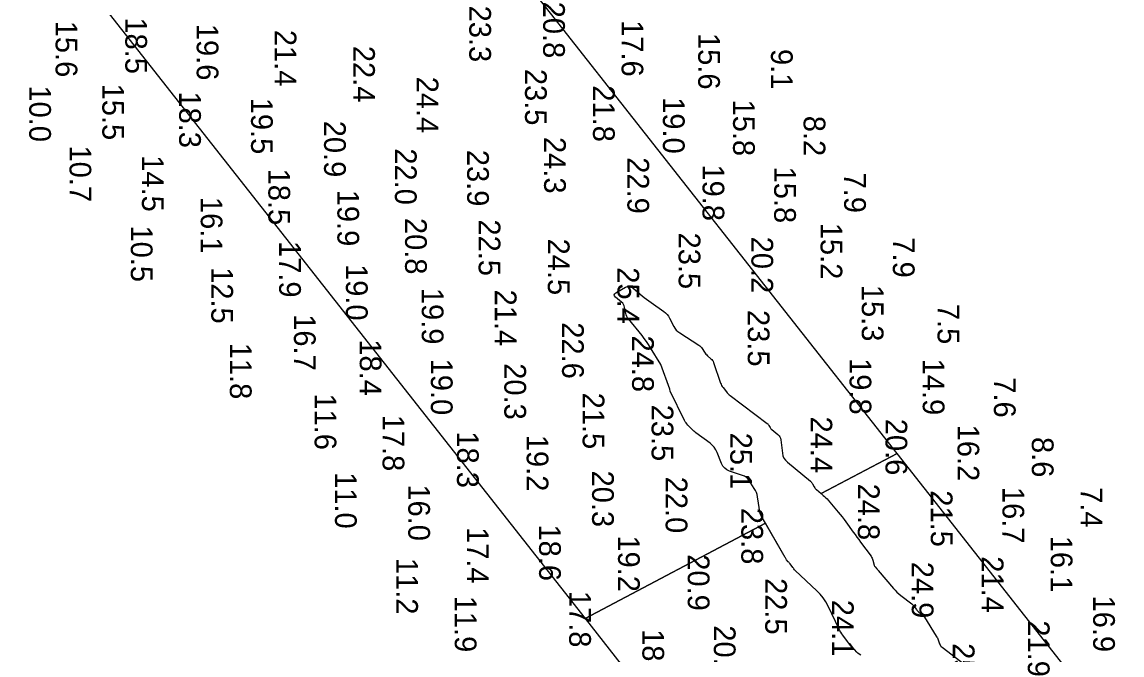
# Model space of a CAD drawing. Extents: x 1178573 to 1187098, y 693282 to 751751.
# Drawn here: x 1183878 to 1184511, y 737960 to 738324 of the extents above; entities that cross this region are included whole.
import ezdxf

# ---------------------------------------------------------------- set-up
doc = ezdxf.new("R2010")
doc.units = 0
for name, color, linetype in [('G-ANNO-PATT', 7, 'Continuous'), ('V-HYDS-MAJR', 7, 'Continuous'), ('V-HYDS-SOUN', 7, 'Continuous')]:
    doc.layers.add(name, color=color, linetype=linetype)

msp = doc.modelspace()

# ---------------------------------------------------------------- linework, layer by layer
at = {"layer": 'G-ANNO-PATT'}
for p, q in [((1184381.59, 738075.66), (1183884.78, 738706.45)), ((1184337.84, 738052.53), (1184381.59, 738075.66)), ((1184381.59, 738075.66), (1184337.84, 738052.53)), ((1184698.75, 737672.97), (1184381.59, 738075.66)), ((1184201.87, 737980.6), (1184305.67, 738035.51)), ((1184305.67, 738035.51), (1184201.87, 737980.6)), ((1184317.07, 738015.86), (1184305.67, 738035.51)), ((1184317.21, 738015.49), (1184317.07, 738015.86)), ((1184317.38, 738015.13), (1184317.21, 738015.49)), ((1184317.59, 738014.8), (1184317.38, 738015.13)), ((1184317.84, 738014.49), (1184317.59, 738014.8)), ((1184318.9, 738013.29), (1184317.84, 738014.49)), ((1184319.17, 738012.99), (1184318.9, 738013.29)), ((1184319.43, 738012.68), (1184319.17, 738012.99)), ((1184319.68, 738012.37), (1184319.43, 738012.68)), ((1184319.92, 738012.05), (1184319.68, 738012.37)), ((1184321.45, 738010.02), (1184319.92, 738012.05)), ((1184321.8, 738009.58), (1184321.45, 738010.02)), ((1184322.16, 738009.16), (1184321.8, 738009.58)), ((1184322.54, 738008.76), (1184322.16, 738009.16)), ((1184322.94, 738008.37), (1184322.54, 738008.76)), ((1184335.35, 737996.66), (1184322.94, 738008.37)), ((1184337.28, 737994.66), (1184335.35, 737996.66)), ((1184339, 737992.52), (1184337.28, 737994.66)), ((1184340.52, 737990.23), (1184339, 737992.52)), ((1184341.83, 737987.79), (1184340.52, 737990.23)), ((1184348.17, 737974.62), (1184341.83, 737987.79)), ((1184201.87, 737980.6), (1184742.06, 737294.73)), ((1184348.65, 737973.67), (1184348.17, 737974.62)), ((1184349.18, 737972.75), (1184348.65, 737973.67)), ((1184349.76, 737971.86), (1184349.18, 737972.75)), ((1184350.38, 737970.99), (1184349.76, 737971.86)), ((1184353.01, 737967.48), (1184350.38, 737970.99)), ((1184353.63, 737966.68), (1184353.01, 737967.48)), ((1184354.26, 737965.89), (1184353.63, 737966.68)), ((1184354.91, 737965.12), (1184354.26, 737965.89)), ((1184355.57, 737964.37), (1184354.91, 737965.12)), ((1184358.27, 737961.37), (1184355.57, 737964.37)), ((1184358.98, 737960.67), (1184358.27, 737961.37)), ((1184359.76, 737960.07), (1184358.98, 737960.67)), ((1184360.6, 737959.58), (1184359.76, 737960.07))]:
    msp.add_line(p, q, dxfattribs=at)
for points in [[(1183555.03, 739077.67), (1183691.64, 738653.74), (1183705.44, 738610.92), (1184201.87, 737980.6)], [(1184305.67, 738035.51), (1184303.49, 738039.27), (1184303.02, 738040.03), (1184302.75, 738040.96), (1184301.2, 738050.68), (1184300.92, 738051.97), (1184300.52, 738053.2), (1184299.99, 738054.39), (1184299.33, 738055.52), (1184296.44, 738059.97), (1184295.66, 738060.99), (1184294.73, 738061.84), (1184293.68, 738062.52), (1184292.48, 738063.03), (1184285.05, 738065.5), (1184283.53, 738066.18), (1184282.26, 738067.13), (1184281.24, 738068.34), (1184280.48, 738069.82), (1184277.91, 738076.25), (1184277.17, 738077.79), (1184276.25, 738079.18), (1184275.14, 738080.43), (1184273.83, 738081.52), (1184265.72, 738087.49), (1184265.08, 738087.99), (1184264.46, 738088.51), (1184263.86, 738089.05), (1184263.29, 738089.63), (1184261.04, 738091.98), (1184260.5, 738092.59), (1184260.02, 738093.23), (1184259.58, 738093.9), (1184259.2, 738094.62), (1184250.93, 738111.42), (1184250.76, 738112.69), (1184245.45, 738126.79), (1184239.6, 738136.48), (1184238.46, 738138.3), (1184237.25, 738140.08), (1184235.99, 738141.81), (1184234.66, 738143.5), (1184226.91, 738152.99), (1184226.38, 738153.72), (1184225.96, 738154.49), (1184225.63, 738155.31), (1184225.39, 738156.18), (1184224.66, 738159.74), (1184224.41, 738160.59), (1184224.04, 738161.37), (1184223.54, 738162.07), (1184222.91, 738162.7), (1184219.46, 738165.62), (1184218.87, 738166.29), (1184218.7, 738166.92), (1184218.97, 738167.51), (1184219.67, 738168.06), (1184225.09, 738171.23), (1184226.28, 738171.74), (1184227.43, 738171.83), (1184228.54, 738171.53), (1184229.62, 738170.81), (1184234.78, 738166.34), (1184236, 738165.31), (1184237.26, 738164.31), (1184238.54, 738163.35), (1184239.84, 738162.42), (1184247.16, 738157.36), (1184248.19, 738156.55), (1184249.1, 738155.64), (1184249.88, 738154.61), (1184250.55, 738153.48), (1184252.96, 738148.74), (1184253.62, 738147.62), (1184254.42, 738146.61), (1184255.34, 738145.72), (1184256.4, 738144.94), (1184267.44, 738137.85), (1184267.97, 738137.47), (1184268.45, 738137.04), (1184268.88, 738136.56), (1184269.26, 738136.03), (1184270.69, 738133.81), (1184271.06, 738133.27), (1184271.47, 738132.77), (1184271.91, 738132.29), (1184272.39, 738131.85), (1184274.38, 738130.13), (1184274.85, 738129.68), (1184275.24, 738129.18), (1184275.56, 738128.63), (1184275.81, 738128.04), (1184279.9, 738116.15), (1184280.18, 738115.44), (1184280.51, 738114.76), (1184280.9, 738114.11), (1184281.35, 738113.49), (1184283.25, 738111.07), (1184283.74, 738110.49), (1184284.27, 738109.94), (1184284.83, 738109.42), (1184285.42, 738108.94), (1184306.77, 738092.81), (1184307.05, 738092.58), (1184307.29, 738092.32), (1184307.51, 738092.04), (1184307.7, 738091.74), (1184308.41, 738090.47), (1184308.6, 738090.16), (1184308.82, 738089.88), (1184309.06, 738089.62), (1184309.33, 738089.38), (1184312.95, 738086.46), (1184313.57, 738085.85), (1184314.05, 738085.17), (1184314.37, 738084.4), (1184314.56, 738083.55), (1184315.5, 738075.83), (1184315.82, 738074.31), (1184316.4, 738072.94), (1184317.24, 738071.71), (1184318.34, 738070.62), (1184331.64, 738059.59), (1184332, 738059.25), (1184332.34, 738058.89), (1184332.63, 738058.5), (1184332.89, 738058.08), (1184333.87, 738056.34), (1184334.13, 738055.92), (1184334.43, 738055.53), (1184334.76, 738055.16), (1184335.12, 738054.83), (1184337.84, 738052.53)], [(1184337.84, 738052.53), (1184339.02, 738051.53), (1184339.78, 738050.86), (1184340.51, 738050.16), (1184341.22, 738049.43), (1184341.89, 738048.67), (1184347.68, 738041.86), (1184348.83, 738040.49), (1184349.95, 738039.09), (1184351.04, 738037.67), (1184352.11, 738036.23), (1184356.32, 738030.43), (1184357.37, 738028.98), (1184358.43, 738027.53), (1184359.48, 738026.09), (1184360.54, 738024.64), (1184366.56, 738016.46), (1184366.89, 738015.96), (1184367.17, 738015.44), (1184367.4, 738014.89), (1184367.57, 738014.32), (1184368.28, 738011.43), (1184368.38, 738011.12), (1184368.51, 738010.83), (1184368.68, 738010.56), (1184368.89, 738010.31), (1184369.78, 738009.33), (1184370.01, 738009.09), (1184370.23, 738008.84), (1184370.45, 738008.59), (1184370.66, 738008.34), (1184379.42, 737998.01), (1184380.42, 737996.89), (1184381.47, 737995.84), (1184382.57, 737994.84), (1184383.73, 737993.9), (1184390.01, 737989.06), (1184390.41, 737988.73), (1184390.79, 737988.37), (1184391.13, 737987.98), (1184391.45, 737987.57), (1184392.66, 737985.87), (1184392.98, 737985.46), (1184393.32, 737985.07), (1184393.69, 737984.71), (1184394.09, 737984.37), (1184395.84, 737982.98), (1184396.25, 737982.63), (1184396.63, 737982.24), (1184396.97, 737981.83), (1184397.28, 737981.38), (1184404.12, 737970.52), (1184404.43, 737970), (1184404.71, 737969.47), (1184404.96, 737968.92), (1184405.19, 737968.35), (1184406.03, 737966.07), (1184406.28, 737965.52), (1184406.59, 737965.03), (1184406.97, 737964.58), (1184407.42, 737964.19), (1184430.65, 737946.34)]]:
    msp.add_lwpolyline(points, dxfattribs=at)
at = {"layer": 'V-HYDS-MAJR'}
msp.add_lwpolyline([(1184360.6, 737959.58), (1184359.76, 737960.07), (1184358.98, 737960.67), (1184358.27, 737961.37), (1184355.57, 737964.37), (1184354.91, 737965.12), (1184354.26, 737965.89), (1184353.63, 737966.68), (1184353.01, 737967.48), (1184350.38, 737970.99), (1184349.76, 737971.86), (1184349.18, 737972.75), (1184348.65, 737973.67), (1184348.17, 737974.62), (1184341.83, 737987.79), (1184340.52, 737990.23), (1184339, 737992.52), (1184337.28, 737994.66), (1184335.35, 737996.66), (1184322.94, 738008.37), (1184322.54, 738008.76), (1184322.16, 738009.16), (1184321.8, 738009.58), (1184321.45, 738010.02), (1184319.92, 738012.05), (1184319.68, 738012.37), (1184319.43, 738012.68), (1184319.17, 738012.99), (1184318.9, 738013.29), (1184317.84, 738014.49), (1184317.59, 738014.8), (1184317.38, 738015.13), (1184317.21, 738015.49), (1184317.07, 738015.86), (1184303.49, 738039.27), (1184303.02, 738040.03), (1184302.75, 738040.96), (1184301.2, 738050.68), (1184300.92, 738051.97), (1184300.52, 738053.2), (1184299.99, 738054.39), (1184299.33, 738055.52), (1184296.44, 738059.97), (1184295.66, 738060.99), (1184294.73, 738061.84), (1184293.68, 738062.52), (1184292.48, 738063.03), (1184285.05, 738065.5), (1184283.53, 738066.18), (1184282.26, 738067.13), (1184281.24, 738068.34), (1184280.48, 738069.82), (1184277.91, 738076.25), (1184277.17, 738077.79), (1184276.25, 738079.18), (1184275.14, 738080.43), (1184273.83, 738081.52), (1184265.72, 738087.49), (1184265.08, 738087.99), (1184264.46, 738088.51), (1184263.86, 738089.05), (1184263.29, 738089.63), (1184261.04, 738091.98), (1184260.5, 738092.59), (1184260.02, 738093.23), (1184259.58, 738093.9), (1184259.2, 738094.62), (1184250.93, 738111.42), (1184250.76, 738112.69), (1184245.45, 738126.79), (1184239.6, 738136.48), (1184238.46, 738138.3), (1184237.25, 738140.08), (1184235.99, 738141.81), (1184234.66, 738143.5), (1184226.91, 738152.99), (1184226.38, 738153.72), (1184225.96, 738154.49), (1184225.63, 738155.31), (1184225.39, 738156.18), (1184224.66, 738159.74), (1184224.41, 738160.59), (1184224.04, 738161.37), (1184223.54, 738162.07), (1184222.91, 738162.7), (1184219.46, 738165.62), (1184218.87, 738166.29), (1184218.7, 738166.92), (1184218.97, 738167.51), (1184219.67, 738168.06), (1184225.09, 738171.23), (1184226.28, 738171.74), (1184227.43, 738171.83), (1184228.54, 738171.53), (1184229.62, 738170.81), (1184234.78, 738166.34), (1184236, 738165.31), (1184237.26, 738164.31), (1184238.54, 738163.35), (1184239.84, 738162.42), (1184247.16, 738157.36), (1184248.19, 738156.55), (1184249.1, 738155.64), (1184249.88, 738154.61), (1184250.55, 738153.48), (1184252.96, 738148.74), (1184253.62, 738147.62), (1184254.42, 738146.61), (1184255.34, 738145.72), (1184256.4, 738144.94), (1184267.44, 738137.85), (1184267.97, 738137.47), (1184268.45, 738137.04), (1184268.88, 738136.56), (1184269.26, 738136.03), (1184270.69, 738133.81), (1184271.06, 738133.27), (1184271.47, 738132.77), (1184271.91, 738132.29), (1184272.39, 738131.85), (1184274.38, 738130.13), (1184274.85, 738129.68), (1184275.24, 738129.18), (1184275.56, 738128.63), (1184275.81, 738128.04), (1184279.9, 738116.15), (1184280.18, 738115.44), (1184280.51, 738114.76), (1184280.9, 738114.11), (1184281.35, 738113.49), (1184283.25, 738111.07), (1184283.74, 738110.49), (1184284.27, 738109.94), (1184284.83, 738109.42), (1184285.42, 738108.94), (1184306.77, 738092.81), (1184307.05, 738092.58), (1184307.29, 738092.32), (1184307.51, 738092.04), (1184307.7, 738091.74), (1184308.41, 738090.47), (1184308.6, 738090.16), (1184308.82, 738089.88), (1184309.06, 738089.62), (1184309.33, 738089.38), (1184312.95, 738086.46), (1184313.57, 738085.85), (1184314.05, 738085.17), (1184314.37, 738084.4), (1184314.56, 738083.55), (1184315.5, 738075.83), (1184315.82, 738074.31), (1184316.4, 738072.94), (1184317.24, 738071.71), (1184318.34, 738070.62), (1184331.64, 738059.59), (1184332, 738059.25), (1184332.34, 738058.89), (1184332.63, 738058.5), (1184332.89, 738058.08), (1184333.87, 738056.34), (1184334.13, 738055.92), (1184334.43, 738055.53), (1184334.76, 738055.16), (1184335.12, 738054.83), (1184339.02, 738051.53), (1184339.78, 738050.86), (1184340.51, 738050.16), (1184341.22, 738049.43), (1184341.89, 738048.67), (1184347.68, 738041.86), (1184348.83, 738040.49), (1184349.95, 738039.09), (1184351.04, 738037.67), (1184352.11, 738036.23), (1184356.32, 738030.43), (1184357.37, 738028.98), (1184358.43, 738027.53), (1184359.48, 738026.09), (1184360.54, 738024.64), (1184366.56, 738016.46), (1184366.89, 738015.96), (1184367.17, 738015.44), (1184367.4, 738014.89), (1184367.57, 738014.32), (1184368.28, 738011.43), (1184368.38, 738011.12), (1184368.51, 738010.83), (1184368.68, 738010.56), (1184368.89, 738010.31), (1184369.78, 738009.33), (1184370.01, 738009.09), (1184370.23, 738008.84), (1184370.45, 738008.59), (1184370.66, 738008.34), (1184379.42, 737998.01), (1184380.42, 737996.89), (1184381.47, 737995.84), (1184382.57, 737994.84), (1184383.73, 737993.9), (1184390.01, 737989.06), (1184390.41, 737988.73), (1184390.79, 737988.37), (1184391.13, 737987.98), (1184391.45, 737987.57), (1184392.66, 737985.87), (1184392.98, 737985.46), (1184393.32, 737985.07), (1184393.69, 737984.71), (1184394.09, 737984.37), (1184395.84, 737982.98), (1184396.25, 737982.63), (1184396.63, 737982.24), (1184396.97, 737981.83), (1184397.28, 737981.38), (1184404.12, 737970.52), (1184404.43, 737970), (1184404.71, 737969.47), (1184404.96, 737968.92), (1184405.19, 737968.35), (1184406.03, 737966.07), (1184406.28, 737965.52), (1184406.59, 737965.03), (1184406.97, 737964.58), (1184407.42, 737964.19), (1184430.65, 737946.34)], dxfattribs=at)

# ---------------------------------------------------------------- texts
at = {"layer": 'V-HYDS-SOUN'}
for s, p in [('23.3 ', (1184135.23, 738333.28)), ('20.8 ', (1184177.75, 738335.54)), ('15.6 ', (1183897.04, 738324.58)), ('18.5 ', (1183937.17, 738326.5)), ('17.6 ', (1184222.89, 738324.91)), ('19.6 ', (1183978.27, 738322.78)), ('21.4 ', (1184023.15, 738319.34)), ('15.6 ', (1184267.02, 738317.53)), ('22.4 ', (1184068.36, 738310.13)), ('9.1', (1184308.92, 738308.32)), ('24.4 ', (1184104.91, 738292.38)), ('23.5 ', (1184167.32, 738296.88)), ('10.0 ', (1183881.85, 738287.36)), ('15.5 ', (1183923.95, 738288.38)), ('21.8 ', (1184206.46, 738287.41)), ('18.3 ', (1183968.17, 738283.93)), ('19.5 ', (1184009.58, 738280.27)), ('19.0 ', (1184246.71, 738280.6)), ('15.8 ', (1184287.1, 738279.24)), ('20.9 ', (1184051.61, 738267.04)), ('8.2', (1184327.72, 738269.89)), ('24.3 ', (1184178.3, 738257.69)), ('10.7 ', (1183905.04, 738252.8)), ('22.0 ', (1184092.41, 738251.17)), ('23.9 ', (1184133.99, 738250.31)), ('14.5 ', (1183946.75, 738247.2)), ('22.9 ', (1184226.25, 738246.04)), ('19.8 ', (1184269.52, 738241.91)), ('18.5 ', (1184019.55, 738239.49)), ('15.8 ', (1184310.76, 738240.66)), ('7.9', (1184351.05, 738237.23)), ('16.1 ', (1183980.61, 738223.2)), ('19.9 ', (1184059.28, 738227.34)), ('20.8 ', (1184098.26, 738211.13)), ('22.5 ', (1184140.62, 738210.26)), ('10.5 ', (1183940.35, 738206.78)), ('15.2 ', (1184337.48, 738208.34)), ('17.9 ', (1184025.75, 738197.85)), ('24.5 ', (1184180.45, 738199.24)), ('23.5 ', (1184255.77, 738202.71)), ('20.2 ', (1184297.65, 738200.34)), ('7.9', (1184379.1, 738199.96)), ('19.0 ', (1184064.2, 738184.6)), ('12.5 ', (1183986.68, 738182.8)), ('25.4 ', (1184220.53, 738182.73)), ('15.3 ', (1184361.21, 738172.62)), ('19.9 ', (1184107.87, 738170.88)), ('21.4 ', (1184149.92, 738169.9)), ('7.5', (1184404.82, 738161.68)), ('16.7 ', (1184034.27, 738155.75)), ('23.5 ', (1184295.57, 738158.16)), ('22.6 ', (1184188.64, 738151.09)), ('18.4 ', (1184072.17, 738141.29)), ('24.8 ', (1184228.97, 738143.48)), ('11.8 ', (1183997.37, 738139.32)), ('19.0 ', (1184113.11, 738130.17)), ('20.3 ', (1184155.4, 738127.54)), ('19.8 ', (1184354.17, 738130.49)), ('14.9 ', (1184396.32, 738130.16)), ('7.6', (1184437.27, 738119.44)), ('11.6 ', (1184046.18, 738110.18)), ('21.5 ', (1184200.49, 738110.62)), ('23.5 ', (1184240.19, 738103.7)), ('17.8 ', (1184085.3, 738097.91)), ('24.4 ', (1184331.68, 738096.87)), ('20.6 ', (1184374.86, 738095.58)), ('16.2 ', (1184416.32, 738092.17)), ('18.3 ', (1184128.14, 738088.33)), ('19.2 ', (1184168.25, 738086.36)), ('25.1 ', (1184285.5, 738087.57)), ('8.6', (1184459.12, 738085.09)), ('11.0 ', (1184057.9, 738064.88)), ('20.3 ', (1184205.93, 738065.79)), ('16.0 ', (1184100.09, 738057.83)), ('22.0 ', (1184248.28, 738062.26)), ('24.8 ', (1184358.96, 738058.28)), ('21.5 ', (1184400.95, 738054.42)), ('16.7 ', (1184442.21, 738056.38)), ('7.4', (1184487.24, 738056.19)), ('23.8 ', (1184291.86, 738044.34)), ('17.4 ', (1184133.81, 738033.26)), ('18.6 ', (1184175.42, 738034.79)), ('19.2 ', (1184220.88, 738028.49)), ('16.1 ', (1184470.01, 738028.28)), ('11.2 ', (1184093.15, 738015.53)), ('20.9 ', (1184261.02, 738017.63)), ('24.9 ', (1184389.99, 738013.3)), ('21.4 ', (1184430.3, 738016.49)), ('22.5 ', (1184305.61, 738003.93)), ('17.8 ', (1184192.75, 737996.57)), ('11.9 ', (1184126.87, 737993.78)), ('24.1 ', (1184344.03, 737991.44)), ('16.9 ', (1184494.42, 737993.88)), ('20.2 ', (1184276.03, 737976.75)), ('21.9 ', (1184456.82, 737979.61)), ('18.2 ', (1184234.89, 737974.55)), ('25.1 ', (1184413.62, 737966.47))]:
    msp.add_text(s, height=12.5, rotation=270, dxfattribs=at).set_placement(p)

doc.saveas('drawing.dxf')
